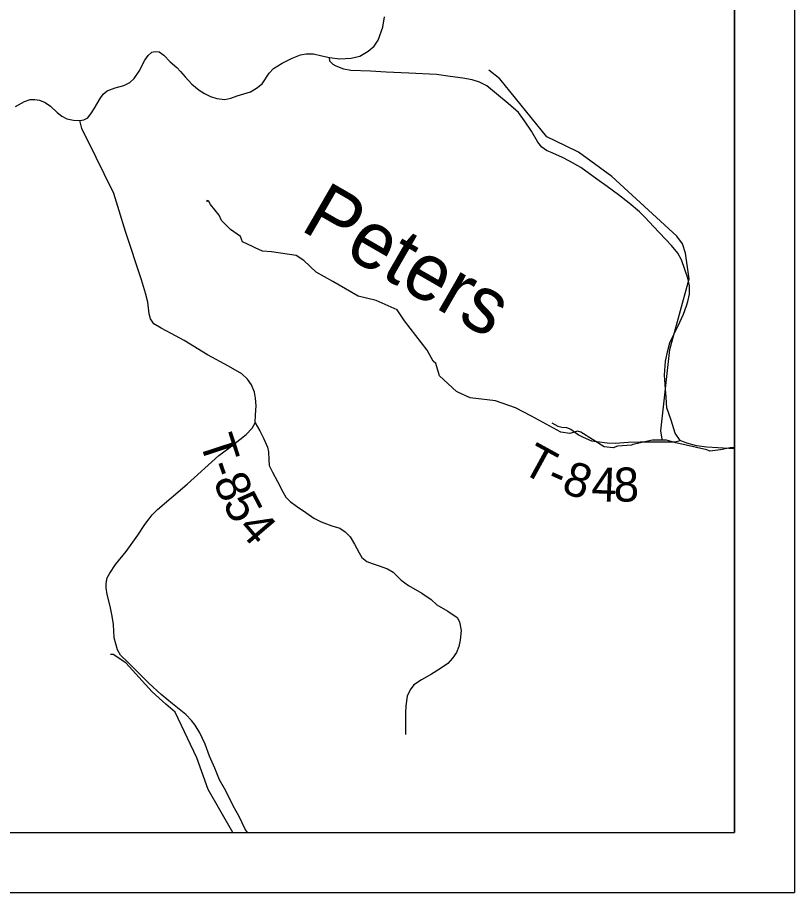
# Model space of a CAD drawing. Extents: x -1.8 to 75.7, y -2 to 25.
# Drawn here: x 7.704 to 9, y 14 to 15.46 of the extents above; entities that cross this region are included whole.
import ezdxf

# ---------------------------------------------------------------- set-up
doc = ezdxf.new("R2010")
doc.units = 0
for name, color, linetype in [('GM_X_County_Road', 7, 'Continuous'), ('GM_X_Minor_River', 7, 'Continuous'), ('GM_X_Minor_River_Text', 7, 'Continuous'), ('GM_X_Township', 7, 'Continuous'), ('GM_X_Township_Road', 7, 'Continuous'), ('GM_X_Township_Road_Text', 7, 'Continuous'), ('SH_Data', 7, 'Continuous')]:
    doc.layers.add(name, color=color, linetype=linetype)

msp = doc.modelspace()

# ---------------------------------------------------------------- linework, layer by layer
at = {"layer": 'GM_X_County_Road'}
for points in [[(7.8081, 15.2879), (7.8153, 15.289), (7.8215, 15.2926), (7.8278, 15.301), (7.8328, 15.3085), (7.8367, 15.3154), (7.842, 15.3248), (7.8474, 15.3323), (7.8541, 15.3375), (7.8675, 15.3425), (7.8816, 15.3466), (7.8919, 15.3517), (7.899, 15.3583), (7.9072, 15.3704), (7.917, 15.3888), (7.9222, 15.3968), (7.9282, 15.402), (7.9339, 15.4034), (7.9405, 15.4027), (7.9482, 15.3973), (7.9592, 15.3861), (7.9701, 15.3763), (7.9763, 15.3699), (7.9838, 15.3612), (7.9952, 15.3487), (8.0075, 15.3389), (8.0164, 15.3332), (8.0264, 15.3282), (8.0367, 15.3248), (8.0499, 15.3234), (8.0599, 15.3252), (8.0709, 15.3291), (8.0929, 15.3361), (8.103, 15.342), (8.1122, 15.3491), (8.124, 15.3669), (8.1311, 15.3749), (8.1459, 15.3836), (8.1623, 15.392), (8.1762, 15.3977), (8.186, 15.3993), (8.1981, 15.3995), (8.212, 15.3961), (8.2245, 15.393), (8.2418, 15.3911), (8.2609, 15.392), (8.2754, 15.3953), (8.2892, 15.4038), (8.2989, 15.4119), (8.3059, 15.422), (8.3134, 15.444), (8.3162, 15.4613)], [(7.701, 15.3115), (7.7162, 15.3199), (7.7257, 15.3229), (7.7331, 15.3232), (7.7411, 15.3221), (7.7504, 15.318), (7.7593, 15.3119), (7.7704, 15.3017), (7.7784, 15.2952), (7.7868, 15.2909), (7.7979, 15.2885), (7.8081, 15.2879)]]:
    msp.add_lwpolyline(points, dxfattribs=at)
at = {"layer": 'GM_X_Minor_River'}
for points in [[(8.7792, 14.7563), (8.7773, 14.7701), (8.7921, 14.9061), (8.8246, 15.0237), (8.8184, 15.0667), (8.8135, 15.0824), (8.8037, 15.095), (8.6955, 15.1945), (8.64, 15.2355), (8.6181, 15.2459), (8.5871, 15.2606), (8.5088, 15.3576), (8.4903, 15.3722)], [(8.9, 14.7424), (8.8929, 14.7419), (8.8766, 14.7388), (8.8589, 14.7365), (8.8539, 14.7388), (8.8021, 14.7505), (8.7866, 14.755), (8.7632, 14.7549), (8.7307, 14.7476), (8.7284, 14.7465), (8.705, 14.7449), (8.6978, 14.7419), (8.6827, 14.7437), (8.6437, 14.768), (8.6384, 14.7695), (8.6256, 14.766), (8.6105, 14.7679), (8.5613, 14.7948), (8.5348, 14.8088), (8.5016, 14.8201), (8.4592, 14.8253), (8.4395, 14.8344), (8.4365, 14.8359), (8.4078, 14.862), (8.4017, 14.8826), (8.3975, 14.8867), (8.3877, 14.9049), (8.3498, 14.9539), (8.3377, 14.9721), (8.3026, 14.9876), (8.2727, 14.9951), (8.2303, 15.0194), (8.2023, 15.0349), (8.1819, 15.0546), (8.169, 15.0629), (8.1278, 15.0689), (8.1127, 15.07), (8.1006, 15.0757), (8.0961, 15.078), (8.0798, 15.0859), (8.076, 15.0943), (8.0598, 15.1064), (8.0446, 15.1212), (8.0408, 15.1303), (8.0265, 15.1477), (8.0227, 15.1538), (8.02, 15.153), (8.0212, 15.1557)], [(8.0636, 14.1), (8.0226, 14.1721), (8.0034, 14.2248), (7.9671, 14.3011), (7.952, 14.3141), (7.9289, 14.335), (7.8853, 14.3834), (7.8642, 14.397), (7.8595, 14.3969)]]:
    msp.add_lwpolyline(points, dxfattribs=at)
at = {"layer": 'GM_X_Township'}
msp.add_lwpolyline([(6.0631, 14.1), (8.9, 14.1), (8.9, 17.0276)], dxfattribs=at)
at = {"layer": 'GM_X_Township_Road'}
for points in [[(8.9, 14.7408), (8.8904, 14.7408), (8.8536, 14.743), (8.8368, 14.7455), (8.8203, 14.7497), (8.8093, 14.754), (8.8013, 14.7665), (8.7942, 14.788), (8.7874, 14.8089), (8.7859, 14.8261), (8.7849, 14.8396), (8.7835, 14.8633), (8.785, 14.8864), (8.7887, 14.9043), (8.7924, 14.9171), (8.7961, 14.9252), (8.8057, 14.9445), (8.8151, 14.9648), (8.8199, 14.9789), (8.8223, 14.9863), (8.8249, 14.9986), (8.8249, 15.0121), (8.8222, 15.0251), (8.8114, 15.0556), (8.8053, 15.0669), (8.7948, 15.0798), (8.7648, 15.1111), (8.7509, 15.1264), (8.7417, 15.1357), (8.7241, 15.15), (8.7064, 15.164), (8.6877, 15.178), (8.6703, 15.1901), (8.644, 15.2097), (8.6248, 15.2204), (8.6133, 15.2263), (8.5969, 15.2335), (8.5863, 15.2383), (8.5789, 15.2437), (8.5719, 15.2522), (8.5614, 15.2701), (8.5497, 15.2873), (8.5396, 15.3012), (8.5225, 15.3164), (8.4868, 15.3458), (8.4746, 15.3523), (8.4624, 15.3561), (8.4471, 15.3585), (8.4258, 15.3617), (8.4032, 15.3648), (8.3572, 15.3669), (8.3193, 15.3689), (8.2932, 15.3706), (8.2601, 15.3715), (8.2483, 15.3735), (8.2355, 15.3787), (8.2305, 15.3818), (8.2251, 15.3872), (8.2245, 15.393)], [(7.924, 14.6237), (7.9289, 14.6302), (7.9377, 14.6388), (7.9872, 14.6814), (8.0404, 14.7292), (8.0566, 14.7415), (8.0859, 14.7641), (8.0956, 14.7748), (8.1005, 14.7838), (8.1012, 14.797), (8.1026, 14.812), (8.1012, 14.825), (8.0996, 14.8349), (8.0947, 14.8469), (8.0882, 14.8564), (8.0787, 14.8653), (8.0563, 14.8781), (8.0212, 14.8971), (7.9821, 14.9209), (7.9608, 14.9325), (7.9437, 14.9417), (7.9317, 14.9489), (7.9264, 14.957), (7.9241, 14.9655), (7.9217, 14.9848), (7.918, 14.9998), (7.9113, 15.022), (7.8843, 15.1027), (7.8739, 15.1376), (7.8653, 15.1663), (7.8491, 15.1991), (7.8355, 15.2266), (7.8119, 15.275), (7.8081, 15.2879)], [(8.1005, 14.7838), (8.1084, 14.7704), (8.1146, 14.7579), (8.1213, 14.7431), (8.1227, 14.735), (8.1234, 14.7221), (8.1243, 14.7123), (8.1298, 14.7013), (8.1377, 14.686), (8.1468, 14.6686), (8.1521, 14.6598), (8.1592, 14.6524), (8.1694, 14.6448), (8.1854, 14.6339), (8.1983, 14.6245), (8.2106, 14.6185), (8.2286, 14.612), (8.242, 14.6078), (8.251, 14.602), (8.2589, 14.5937), (8.2665, 14.5812), (8.2739, 14.5669), (8.2788, 14.5592), (8.2871, 14.5523), (8.2959, 14.5491), (8.3075, 14.5451), (8.3213, 14.5401), (8.3306, 14.5343), (8.344, 14.5209), (8.3563, 14.5125), (8.3784, 14.4995), (8.394, 14.4889), (8.4037, 14.4799), (8.4222, 14.4695), (8.4374, 14.4591), (8.4414, 14.4515), (8.4441, 14.4371), (8.4425, 14.4212), (8.4402, 14.4106), (8.4365, 14.4006), (8.43, 14.3909), (8.4217, 14.3823), (8.4095, 14.374), (8.3947, 14.3645), (8.3778, 14.3551), (8.3655, 14.3463), (8.359, 14.3382), (8.3544, 14.3275), (8.3521, 14.3113), (8.3514, 14.2998), (8.3516, 14.2639)], [(8.5955, 14.7835), (8.6055, 14.7783), (8.6119, 14.7762), (8.6198, 14.7756), (8.627, 14.773), (8.64, 14.7639), (8.6476, 14.7597), (8.6613, 14.7536), (8.6704, 14.7524), (8.6876, 14.7503), (8.7015, 14.7497), (8.7228, 14.7512), (8.7425, 14.7518), (8.7701, 14.7521), (8.8005, 14.7518), (8.8093, 14.754)], [(8.0877, 14.1), (8.0843, 14.1055), (8.0739, 14.1268), (8.0642, 14.1446), (8.0519, 14.1696), (8.0415, 14.1879), (8.0332, 14.2073), (8.0244, 14.2276), (8.0172, 14.2475), (8.0082, 14.2662), (8.0004, 14.279), (7.9944, 14.2868), (7.9849, 14.297), (7.9627, 14.315), (7.9439, 14.3303), (7.9234, 14.349), (7.906, 14.3666), (7.8884, 14.3844), (7.8764, 14.3962), (7.8709, 14.405), (7.8658, 14.4247), (7.8646, 14.4471), (7.8623, 14.4612), (7.8591, 14.4776), (7.8542, 14.497), (7.8524, 14.5081), (7.8525, 14.5158), (7.8538, 14.525), (7.8581, 14.5329), (7.8679, 14.5475), (7.8857, 14.569), (7.9049, 14.5962), (7.9169, 14.6141), (7.924, 14.6237)]]:
    msp.add_lwpolyline(points, dxfattribs=at)
at = {"layer": 'SH_Data'}
for p, q in [((9, 21), (9, 14)), ((8.9, 20.9), (8.9, 14.1)), ((2.1, 14.1), (8.9, 14.1)), ((2, 14), (9, 14))]:
    msp.add_line(p, q, dxfattribs=at)

# ---------------------------------------------------------------- texts
at = {"layer": 'GM_X_Minor_River_Text'}
msp.add_text('Peters', height=0.0947, rotation=329.9981, dxfattribs=at).set_placement((8.1738, 15.1065))
at = {"layer": 'GM_X_Township_Road_Text'}
for s, rotation, p in [('T', 288.1334, (8.0073, 14.7536)), ('T', 331.284, (8.5417, 14.7025)), ('-', 289.1162, (8.0209, 14.7122)), ('8', 340.4651, (8.6094, 14.6686)), ('4', 357.7233, (8.6607, 14.6534)), ('8', 0.7219, (8.6989, 14.652)), ('8', 292.8593, (8.03, 14.6864)), ('-', 336.2262, (8.5838, 14.6797)), ('5', 297.6236, (8.0457, 14.6495)), ('4', 310.4716, (8.0697, 14.607))]:
    msp.add_text(s, height=0.0568, rotation=rotation, dxfattribs=at).set_placement(p)

doc.saveas('drawing.dxf')
